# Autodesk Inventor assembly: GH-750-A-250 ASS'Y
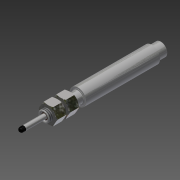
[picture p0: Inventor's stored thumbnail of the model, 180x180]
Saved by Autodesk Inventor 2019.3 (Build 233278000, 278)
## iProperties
Created: 2018-10
Part Number: GH-750-A-250 ASS'Y
Document SubType Name: Weldment
Designer: Justin
Weld Material: Stainless Steel
Author: Justin
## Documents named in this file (4)
- C:\Users\Justin\Documents\CAD Drawings\The Sensor Connection\3D\LVDT\GH SERIES\GH-750-A-XXXX\GH-750-A-250\GH-750-A-250 ASS'Y.iam
- C:\Users\Justin\Documents\CAD Drawings\The Sensor Connection\3D\LVDT\GH SERIES\GH-750-A-XXXX\GH-750-A-250\GH-750-A-250 HOUSING_SW.ipt
- C:\Users\Justin\Documents\CAD Drawings\The Sensor Connection\3D\LVDT\GH SERIES\GH-750-A-XXXX\GH-750-A-250\AS 2465 - 1_2  UNF(1).ipt
- C:\Users\Justin\Documents\CAD Drawings\The Sensor Connection\3D\LVDT\GH SERIES\GH-750-A-XXXX\GH-750-A-050\GH-750-A-050 SHAFT_SW.ipt
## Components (4 placed, 3 different names)
1. GH-750-A-250 HOUSING_SW:1 — Cylindrical:1, Mate:4, Mate:5
2. GH-750-A-050 SHAFT_SW:1 — Cylindrical:1
3. AS 2465 - Inch 1/2  UNF:1 — Mate:2, Mate:3, Angle:1, Mate:4, Mate:5
4. AS 2465 - Inch 1/2  UNF:2 — Mate:2, Mate:3, Angle:1, Angle:2
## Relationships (7: Mate 4, Angle 2, CylindricalJoint 1)
- Cylindrical:1: GH-750-A-250 HOUSING_SW:1 ↔ GH-750-A-050 SHAFT_SW:1
- Mate:2: AS 2465 - Inch 1/2  UNF:1 ↔ AS 2465 - Inch 1/2  UNF:2
- Mate:3: AS 2465 - Inch 1/2  UNF:1 ↔ AS 2465 - Inch 1/2  UNF:2
- Angle:1: AS 2465 - Inch 1/2  UNF:1 ↔ AS 2465 - Inch 1/2  UNF:2
- Mate:4: GH-750-A-250 HOUSING_SW:1 ↔ AS 2465 - Inch 1/2  UNF:1
- Mate:5: GH-750-A-250 HOUSING_SW:1 ↔ AS 2465 - Inch 1/2  UNF:1
- Angle:2: AS 2465 - Inch 1/2  UNF:2
